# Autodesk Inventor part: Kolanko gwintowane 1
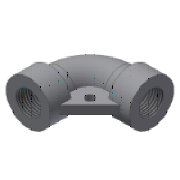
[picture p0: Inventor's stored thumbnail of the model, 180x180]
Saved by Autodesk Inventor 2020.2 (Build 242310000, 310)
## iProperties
Manager: www.cadconsulting.pl
Company: Fabian Stasiak CAD Consulting
Created: 2014-08
Part Number: Kolanko gwintowane 1
Material: Ogólny
Document SubType Name: Modeling
Designer: F.Stasiak
Standards Organization: ANSI
Language: pl-PL
Size Designation: 1
Categories: <MemberInstance><Categories><Category DisplayName="Rury cienko- i grubościenne" InternalName="4347fa0f-2144-441d-94cd-e3e15c92b736" Mnemonic="TUBEANDPIPE"><Cate
Density: 1 g/cm^3
Appearance: Domyślna
Catalog Web Link: www.expertbooks.pl
IsCustomPart: 0
Author: F.Stasiak
Subject: Zbiór ćwiczeń. Autodesk Inventor 2020. Kurs Professional
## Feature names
1. Przeciągnięcie1
2. Wyciągnięcie proste1 [Extrusion]
3. Wyciągnięcie proste2 [Extrusion]
4. Wyciągnięcie proste5 [Extrusion]
## Parameters: d0 = 74.2315 mm, d1 = 74.2315 mm, d2 = 37.11575 mm, d4 = 0, d5 = 0, d6 = 45.974 mm, d7 = 29.6926 mm, d9 = 20.955 mm, d10 = 0, d11 = 45.974 mm, d12 = 20.955 mm, d13 = 0, d19 = 19.8628 mm, d20 = 0, d21 = 19.8628 mm, d22 = 0, ID = 29.6926 mm, OD = 45.974 mm, GL = 20.955 mm, G = 3.683 mm, d23 = 3.683 mm, d24 = 6.35 mm, d26 = 7.366 mm, d27 = 0
